(* Logix 5000 project; controller DL232_Example vendor 1 type 14 code 96 rev 19.13; software revision 19.01 *)

TASK MainTask (continuous, watchdog 500 ms) : MainProgram

MODULES
   Local : vendor 1 type 14 code 96 (ICP 0, rev 19.13)
      EtherNet_Bridge : vendor 1 type 12 code 200 (ICP 1, Ethernet 192.168.1.6, rev 3.6)
         DL232 : ETHERNET-MODULE (Ethernet 192.168.1.173, rev 1.1, Output RPI 500 ms)
END_MODULES

TYPE ProSoftPLX51DL232DataSource :
STRUCT
   EtherNetIP : BOOL;
   DF1 : BOOL;
   ModbusRTU : BOOL;
   ModbusTCP : BOOL;
END_STRUCT
END_TYPE

TYPE ProSoftPLX51DL232Input :
STRUCT
   Instance : STRING;
   Status : ProSoftPLX51DL232Status;
   CachePercentageUsed : REAL;
   CacheRecordCount : DINT;
   TotalRecordCount : DINT;
   ActiveTagCount : DINT;
   DataSource : ProSoftPLX51DL232DataSource;
   DataSourceReadCount : DINT;
END_STRUCT
END_TYPE

TYPE ProSoftPLX51DL232Status :
STRUCT
   Running : BOOL;
   ConfigurationValid : BOOL;
   ContinuousLogging : BOOL;
   LogRollover : BOOL;
   LoggingInhibited : BOOL;
   LoggingStopped : BOOL;
END_STRUCT
END_TYPE

VAR_GLOBAL   (* controller tags *)
   DL232Input : ProSoftPLX51DL232Input := (Instance := 'Data Logger', Status.Running := 1, Status.ConfigurationValid := 1, Status.ContinuousLogging := 1, CachePercentageUsed := 0.00059604645, CacheRecordCount := 100, TotalRecordCount := 100, ActiveTagCount := 100, DataSource.EtherNetIP := 1, DataSourceReadCount := 4000);
END_VAR

PROGRAM MainProgram   (* main routine MainRoutine *)

ROUTINE DL232_Routine   (* ladder *)
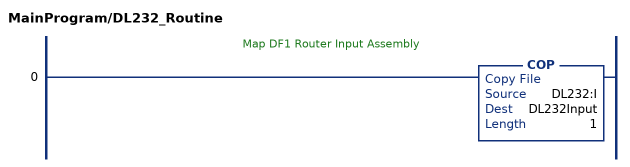
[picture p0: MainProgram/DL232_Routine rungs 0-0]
   // Map DF1 Router Input Assembly
   0: COP(DL232:I,DL232Input,1);
END_ROUTINE

ROUTINE MainRoutine   (* ladder *)
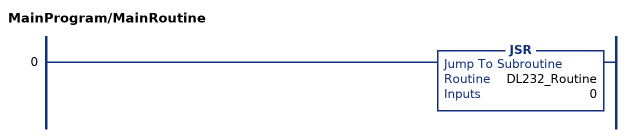
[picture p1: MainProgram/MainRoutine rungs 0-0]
   0: JSR(DL232_Routine,0);
END_ROUTINE
END_PROGRAM
